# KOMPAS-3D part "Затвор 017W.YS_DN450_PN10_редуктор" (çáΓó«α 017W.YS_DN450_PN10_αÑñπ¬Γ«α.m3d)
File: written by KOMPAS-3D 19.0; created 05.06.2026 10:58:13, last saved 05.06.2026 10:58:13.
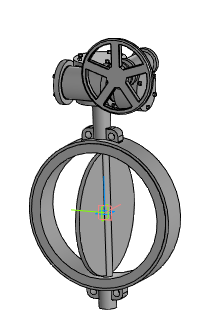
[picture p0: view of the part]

Document properties: Автор: Энергия; Полное имя файла: ..\..\..\3d для проектировщиков\x.x Тип 017W.Y(S) Затвор дисковый поворотный межфланцевый\Затвор 017W.Y(S)_DN50-DN1200_редуктор\Затвор 017W.YS_DN450_PN10_редуктор.a3d

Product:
- Part/product: Затвор 017W.YS_DN450_PN10_редуктор
    Масса: 152.31

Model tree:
1. Операция без истории:1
